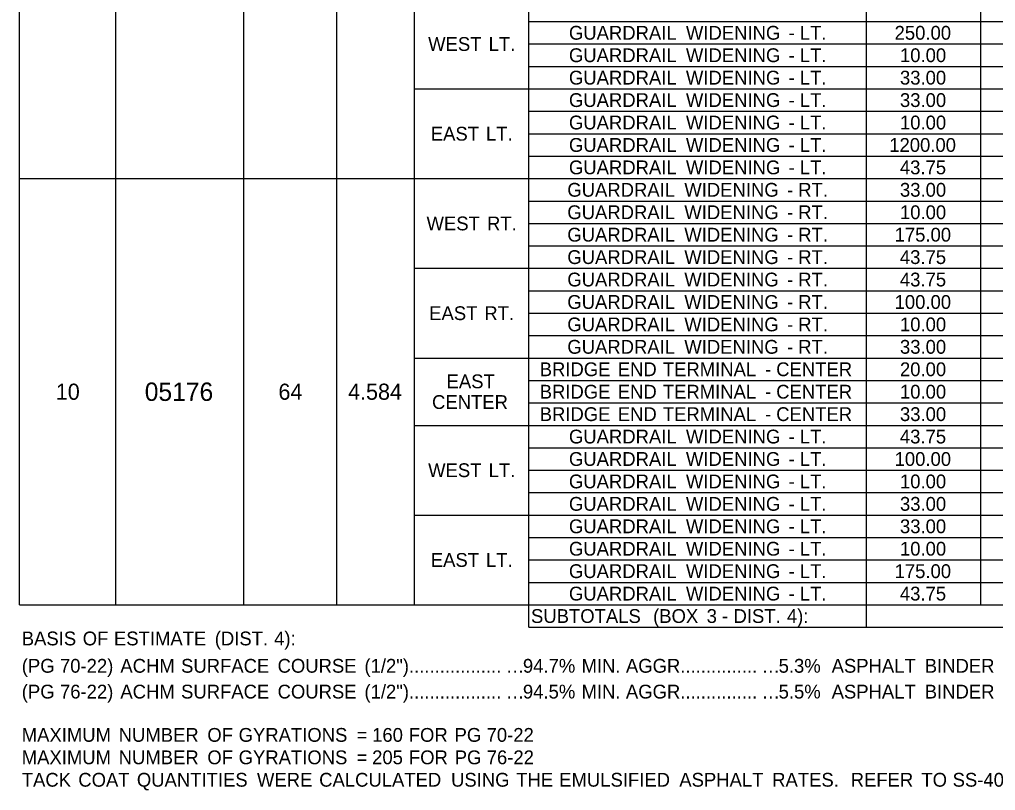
# Model space of a CAD drawing. Extents: x 540541 to 1930787, y -1948574 to 596640.
# Drawn here: x 557868.7 to 558292.9, y -1946902.7 to -1946567.6 of the extents above; entities that cross this region are included whole.
import ezdxf

# ---------------------------------------------------------------- set-up
doc = ezdxf.new("R2010")
doc.units = 0
doc.layers.add('Default', color=7, linetype='Continuous')

msp = doc.modelspace()

# ---------------------------------------------------------------- linework, layer by layer
at = {"layer": 'Default'}
for p, q in [((557868.72, -1946821.96), (557868.72, -1946237.94)), ((557910.65, -1946821.96), (557910.65, -1946237.94)), ((557966.22, -1946821.96), (557966.22, -1946237.94)), ((558006.68, -1946821.96), (558006.68, -1946237.94)), ((558040.32, -1946821.96), (558040.32, -1946237.94)), ((558090.05, -1946831.71), (558090.05, -1946237.94)), ((558236.78, -1946831.71), (558236.78, -1946237.94)), ((558286.51, -1946821.96), (558286.51, -1946237.94)), ((558286.51, -1946704.96), (558286.51, -1946285.71)), ((557966.22, -1946821.96), (557966.22, -1946295.46)), ((558236.78, -1946685.46), (558236.78, -1946363.71)), ((558090.05, -1946568.46), (558755.48, -1946568.46)), ((558090.05, -1946578.21), (558755.48, -1946578.21)), ((558090.05, -1946587.96), (558755.48, -1946587.96)), ((558040.32, -1946597.71), (558388.4, -1946597.71)), ((558090.05, -1946607.46), (558755.48, -1946607.46)), ((558090.05, -1946617.21), (558388.4, -1946617.21)), ((558090.05, -1946626.96), (558388.4, -1946626.96)), ((557868.72, -1946636.71), (557910.65, -1946636.71)), ((557868.72, -1946636.71), (558755.48, -1946636.71)), ((557966.22, -1946636.71), (558040.32, -1946636.71)), ((558040.32, -1946636.71), (558755.48, -1946636.71)), ((558090.05, -1946646.46), (558755.48, -1946646.46)), ((558090.05, -1946656.21), (558755.48, -1946656.21)), ((558090.05, -1946665.96), (558755.48, -1946665.96)), ((558040.32, -1946675.71), (558755.48, -1946675.71)), ((558090.05, -1946685.46), (558090.05, -1946675.71)), ((558090.05, -1946685.46), (558755.48, -1946685.46)), ((558090.05, -1946695.21), (558236.78, -1946695.21)), ((558090.05, -1946695.21), (558755.48, -1946695.21)), ((558090.05, -1946704.96), (558755.48, -1946704.96)), ((558090.05, -1946743.96), (558090.05, -1946704.96)), ((558236.78, -1946714.71), (558236.78, -1946704.96)), ((558040.32, -1946714.71), (558755.48, -1946714.71)), ((558286.51, -1946821.96), (558286.51, -1946714.71)), ((558090.05, -1946724.46), (558755.48, -1946724.46)), ((558090.05, -1946734.21), (558755.48, -1946734.21)), ((558040.32, -1946743.96), (558755.48, -1946743.96)), ((558236.78, -1946831.71), (558236.78, -1946743.96)), ((558090.05, -1946753.71), (558755.48, -1946753.71)), ((558090.05, -1946763.46), (558755.48, -1946763.46)), ((558090.05, -1946773.21), (558755.48, -1946773.21)), ((558040.32, -1946782.96), (558388.4, -1946782.96)), ((558090.05, -1946792.71), (558755.48, -1946792.71)), ((558090.05, -1946802.46), (558755.48, -1946802.46)), ((558090.05, -1946812.21), (558388.4, -1946812.21)), ((557868.72, -1946821.96), (558755.48, -1946821.96)), ((558090.05, -1946821.96), (558528.31, -1946821.96)), ((558090.05, -1946831.71), (558090.05, -1946821.96)), ((558090.05, -1946831.71), (558755.48, -1946831.71))]:
    msp.add_line(p, q, dxfattribs=at)

# ---------------------------------------------------------------- texts
for s, height, p in [('GUARDRAIL', 6, (558107.5, -1946576.34)), (' WIDENING', 6, (558156.12, -1946576.34)), (' -', 6, (558200.77, -1946576.34)), (' LT.', 6, (558205.62, -1946576.34)), ('250.00', 6, (558249.03, -1946576.34)), ('WEST', 6, (558046.31, -1946581.21)), (' LT.', 6, (558070.36, -1946581.21)), ('GUARDRAIL', 6, (558107.5, -1946586.09)), (' WIDENING', 6, (558156.12, -1946586.09)), (' LT.', 6, (558205.62, -1946586.09)), ('10.00', 6, (558251.36, -1946586.09)), (' -', 6, (558200.77, -1946586.09)), ('GUARDRAIL', 6, (558107.5, -1946595.84)), (' WIDENING', 6, (558156.12, -1946595.84)), (' LT.', 6, (558205.62, -1946595.84)), ('33.00', 6, (558251.36, -1946595.84)), (' -', 6, (558200.77, -1946595.84)), ('GUARDRAIL', 6, (558107.5, -1946605.59)), (' WIDENING', 6, (558156.12, -1946605.59)), (' LT.', 6, (558205.62, -1946605.59)), ('33.00', 6, (558251.36, -1946605.59)), (' -', 6, (558200.77, -1946605.59)), ('GUARDRAIL', 6, (558107.5, -1946615.34)), (' WIDENING', 6, (558156.12, -1946615.34)), (' LT.', 6, (558205.62, -1946615.34)), ('10.00', 6, (558251.36, -1946615.34)), ('EAST', 6, (558047.46, -1946620.21)), (' LT.', 6, (558069.2, -1946620.21)), (' -', 6, (558200.77, -1946615.34)), ('GUARDRAIL', 6, (558107.5, -1946625.09)), (' WIDENING', 6, (558156.12, -1946625.09)), (' LT.', 6, (558205.62, -1946625.09)), ('1200.00', 6, (558246.7, -1946625.09)), (' -', 6, (558200.77, -1946625.09)), ('GUARDRAIL', 6, (558107.5, -1946634.84)), (' WIDENING', 6, (558156.12, -1946634.84)), (' LT.', 6, (558205.62, -1946634.84)), ('43.75', 6, (558251.33, -1946634.84)), (' -', 6, (558200.77, -1946634.84)), ('GUARDRAIL', 6, (558106.8, -1946644.59)), (' WIDENING', 6, (558155.42, -1946644.59)), (' -', 6, (558200.07, -1946644.59)), (' RT.', 6, (558204.93, -1946644.59)), ('33.00', 6, (558251.36, -1946644.59)), ('GUARDRAIL', 6, (558106.8, -1946654.34)), (' WIDENING', 6, (558155.42, -1946654.34)), (' RT.', 6, (558204.93, -1946654.34)), ('10.00', 6, (558251.36, -1946654.34)), ('WEST', 6, (558045.61, -1946659.21)), (' RT.', 6, (558069.66, -1946659.21)), (' -', 6, (558200.07, -1946654.34)), ('GUARDRAIL', 6, (558106.8, -1946664.09)), (' WIDENING', 6, (558155.42, -1946664.09)), (' RT.', 6, (558204.93, -1946664.09)), ('175.00', 6, (558249.03, -1946664.09)), (' -', 6, (558200.07, -1946664.09)), ('GUARDRAIL', 6, (558106.8, -1946673.84)), (' WIDENING', 6, (558155.42, -1946673.84)), (' -', 6, (558200.07, -1946673.84)), (' RT.', 6, (558204.93, -1946673.84)), ('43.75', 6, (558251.33, -1946673.84)), ('GUARDRAIL', 6, (558106.8, -1946683.59)), (' WIDENING', 6, (558155.42, -1946683.59)), (' RT.', 6, (558204.93, -1946683.59)), ('43.75', 6, (558251.33, -1946683.59)), (' -', 6, (558200.07, -1946683.59)), ('GUARDRAIL', 6, (558106.8, -1946693.34)), (' WIDENING', 6, (558155.42, -1946693.34)), (' RT.', 6, (558204.93, -1946693.34)), ('100.00', 6, (558249.03, -1946693.34)), ('EAST', 6, (558046.77, -1946698.21)), (' RT.', 6, (558068.5, -1946698.21)), (' -', 6, (558200.07, -1946693.34)), ('GUARDRAIL', 6, (558106.8, -1946703.09)), (' WIDENING', 6, (558155.42, -1946703.09)), (' RT.', 6, (558204.93, -1946703.09)), ('10.00', 6, (558251.36, -1946703.09)), (' -', 6, (558200.07, -1946703.09)), ('GUARDRAIL', 6, (558106.8, -1946712.84)), (' WIDENING', 6, (558155.42, -1946712.84)), (' RT.', 6, (558204.93, -1946712.84)), ('33.00', 6, (558251.36, -1946712.84)), (' -', 6, (558200.07, -1946712.84)), ('BRIDGE', 6, (558094.79, -1946722.59)), (' END', 6, (558126.49, -1946722.59)), (' TERMINAL', 6, (558146.07, -1946722.59)), (' CENTER', 6, (558195.35, -1946722.59)), ('20.00', 6, (558251.36, -1946722.59)), ('EAST', 6, (558054.32, -1946727.84)), (' -', 6, (558190.49, -1946722.59)), ('10', 7, (557884.48, -1946732.84)), ('05176', 8, (557923.15, -1946733.34)), ('64', 7, (557981.25, -1946732.84)), ('4.584', 7, (558011.51, -1946732.84)), ('BRIDGE', 6, (558094.79, -1946732.34)), (' END', 6, (558126.49, -1946732.34)), (' TERMINAL', 6, (558146.07, -1946732.34)), (' CENTER', 6, (558195.35, -1946732.34)), ('10.00', 6, (558251.36, -1946732.34)), ('CENTER', 6, (558048, -1946736.84)), (' -', 6, (558190.49, -1946732.34)), ('BRIDGE', 6, (558094.79, -1946742.09)), (' END', 6, (558126.49, -1946742.09)), (' TERMINAL', 6, (558146.07, -1946742.09)), (' -', 6, (558190.49, -1946742.09)), (' CENTER', 6, (558195.35, -1946742.09)), ('33.00', 6, (558251.36, -1946742.09)), ('GUARDRAIL', 6, (558107.5, -1946751.84)), (' WIDENING', 6, (558156.12, -1946751.84)), (' LT.', 6, (558205.62, -1946751.84)), ('43.75', 6, (558251.33, -1946751.84)), (' -', 6, (558200.77, -1946751.84)), ('GUARDRAIL', 6, (558107.5, -1946761.59)), (' WIDENING', 6, (558156.12, -1946761.59)), (' LT.', 6, (558205.62, -1946761.59)), ('100.00', 6, (558249.03, -1946761.59)), ('WEST', 6, (558046.31, -1946766.46)), (' LT.', 6, (558070.36, -1946766.46)), (' -', 6, (558200.77, -1946761.59)), ('GUARDRAIL', 6, (558107.5, -1946771.34)), (' WIDENING', 6, (558156.12, -1946771.34)), (' -', 6, (558200.77, -1946771.34)), (' LT.', 6, (558205.62, -1946771.34)), ('10.00', 6, (558251.36, -1946771.34)), ('GUARDRAIL', 6, (558107.5, -1946781.09)), (' WIDENING', 6, (558156.12, -1946781.09)), (' LT.', 6, (558205.62, -1946781.09)), ('33.00', 6, (558251.36, -1946781.09)), (' -', 6, (558200.77, -1946781.09)), ('GUARDRAIL', 6, (558107.5, -1946790.84)), (' WIDENING', 6, (558156.12, -1946790.84)), (' LT.', 6, (558205.62, -1946790.84)), ('33.00', 6, (558251.36, -1946790.84)), (' -', 6, (558200.77, -1946790.84)), ('GUARDRAIL', 6, (558107.5, -1946800.59)), (' WIDENING', 6, (558156.12, -1946800.59)), (' LT.', 6, (558205.62, -1946800.59)), ('10.00', 6, (558251.36, -1946800.59)), (' -', 6, (558200.77, -1946800.59)), ('EAST', 6, (558047.46, -1946805.46)), (' LT.', 6, (558069.2, -1946805.46)), ('GUARDRAIL', 6, (558107.5, -1946810.34)), (' WIDENING', 6, (558156.12, -1946810.34)), (' LT.', 6, (558205.62, -1946810.34)), ('175.00', 6, (558249.03, -1946810.34)), (' -', 6, (558200.77, -1946810.34)), ('GUARDRAIL', 6, (558107.5, -1946820.09)), (' WIDENING', 6, (558156.12, -1946820.09)), (' LT.', 6, (558205.62, -1946820.09)), ('43.75', 6, (558251.33, -1946820.09)), (' -', 6, (558200.77, -1946820.09)), ('SUBTOTALS', 6, (558091.02, -1946829.84)), (' (BOX', 6, (558141.85, -1946829.84)), (' 3', 6, (558165.12, -1946829.84)), (' DIST.', 6, (558176.81, -1946829.84)), (' 4):', 6, (558199.99, -1946829.84)), (' -', 6, (558171.75, -1946829.84)), ('BASIS', 6, (557869.7, -1946839.59)), (' OF', 6, (557893.96, -1946839.59)), (' ESTIMATE', 6, (557907.54, -1946839.59)), (' (DIST.', 6, (557951.35, -1946839.59)), (' 4):', 6, (557977.16, -1946839.59)), ('(PG', 6, (557869.7, -1946851.48)), (' 70-22)', 6, (557884.07, -1946851.48)), (' ACHM', 6, (557910.32, -1946851.48)), (' SURFACE', 6, (557936.7, -1946851.48)), (' COURSE', 6, (557978.65, -1946851.48)), (' (1/2")..................', 6, (558016.4, -1946851.48)), ('94.7%', 6, (558087.5, -1946851.48)), (' MIN.', 6, (558110.74, -1946851.48)), (' AGGR...............', 6, (558130.03, -1946851.48)), ('5.3%', 6, (558198.63, -1946851.48)), ('  ASPHALT', 6, (558217.21, -1946851.48)), (' BINDER', 6, (558259.91, -1946851.48)), ('…', 6, (558080.1, -1946851.48)), ('…', 6, (558191.23, -1946851.48)), ('(PG', 6, (557869.7, -1946862.69)), (' 76-22)', 6, (557884.07, -1946862.69)), (' ACHM', 6, (557910.32, -1946862.69)), (' SURFACE', 6, (557936.7, -1946862.69)), (' COURSE', 6, (557978.65, -1946862.69)), (' (1/2")..................', 6, (558016.4, -1946862.69)), ('94.5%', 6, (558087.5, -1946862.69)), (' MIN.', 6, (558110.74, -1946862.69)), (' AGGR...............', 6, (558130.03, -1946862.69)), ('5.5%', 6, (558198.63, -1946862.69)), ('  ASPHALT', 6, (558217.21, -1946862.69)), (' BINDER', 6, (558259.91, -1946862.69)), ('…', 6, (558080.1, -1946862.69)), ('…', 6, (558191.23, -1946862.69)), (' OF', 6, (557948.13, -1946881.51)), (' GYRATIONS', 6, (557961.72, -1946881.51)), (' 160', 6, (558019.74, -1946881.51)), (' FOR', 6, (558035.65, -1946881.51)), (' PG', 6, (558055.56, -1946881.51)), (' 70-22', 6, (558069.47, -1946881.51)), ('MAXIMUM', 6, (557869.7, -1946881.51)), (' NUMBER', 6, (557909.58, -1946881.51)), (' =', 6, (558012.99, -1946881.51)), ('MAXIMUM', 6, (557869.7, -1946891.26)), (' NUMBER', 6, (557909.58, -1946891.26)), (' OF', 6, (557948.13, -1946891.26)), (' GYRATIONS', 6, (557961.72, -1946891.26)), (' =', 6, (558012.99, -1946891.26)), (' 205', 6, (558019.74, -1946891.26)), (' FOR', 6, (558035.72, -1946891.26)), (' PG', 6, (558055.63, -1946891.26)), (' 76-22', 6, (558069.54, -1946891.26)), ('TACK', 6, (557869.7, -1946901.01)), (' COAT', 6, (557892.04, -1946901.01)), (' QUANTITIES', 6, (557917.49, -1946901.01)), (' WERE', 6, (557969.69, -1946901.01)), (' CALCULATED', 6, (557996.72, -1946901.01)), (' USING', 6, (558054.04, -1946901.01)), (' THE', 6, (558082.39, -1946901.01)), (' EMULSIFIED', 6, (558101.04, -1946901.01)), (' ASPHALT', 6, (558153.23, -1946901.01)), (' RATES.', 6, (558193.6, -1946901.01)), ('  REFER', 6, (558225.48, -1946901.01)), (' TO', 6, (558258.44, -1946901.01)), (' SS-400-1', 6, (558272.03, -1946901.01))]:
    msp.add_text(s, height=height, dxfattribs=at).set_placement(p)

doc.saveas('drawing.dxf')
